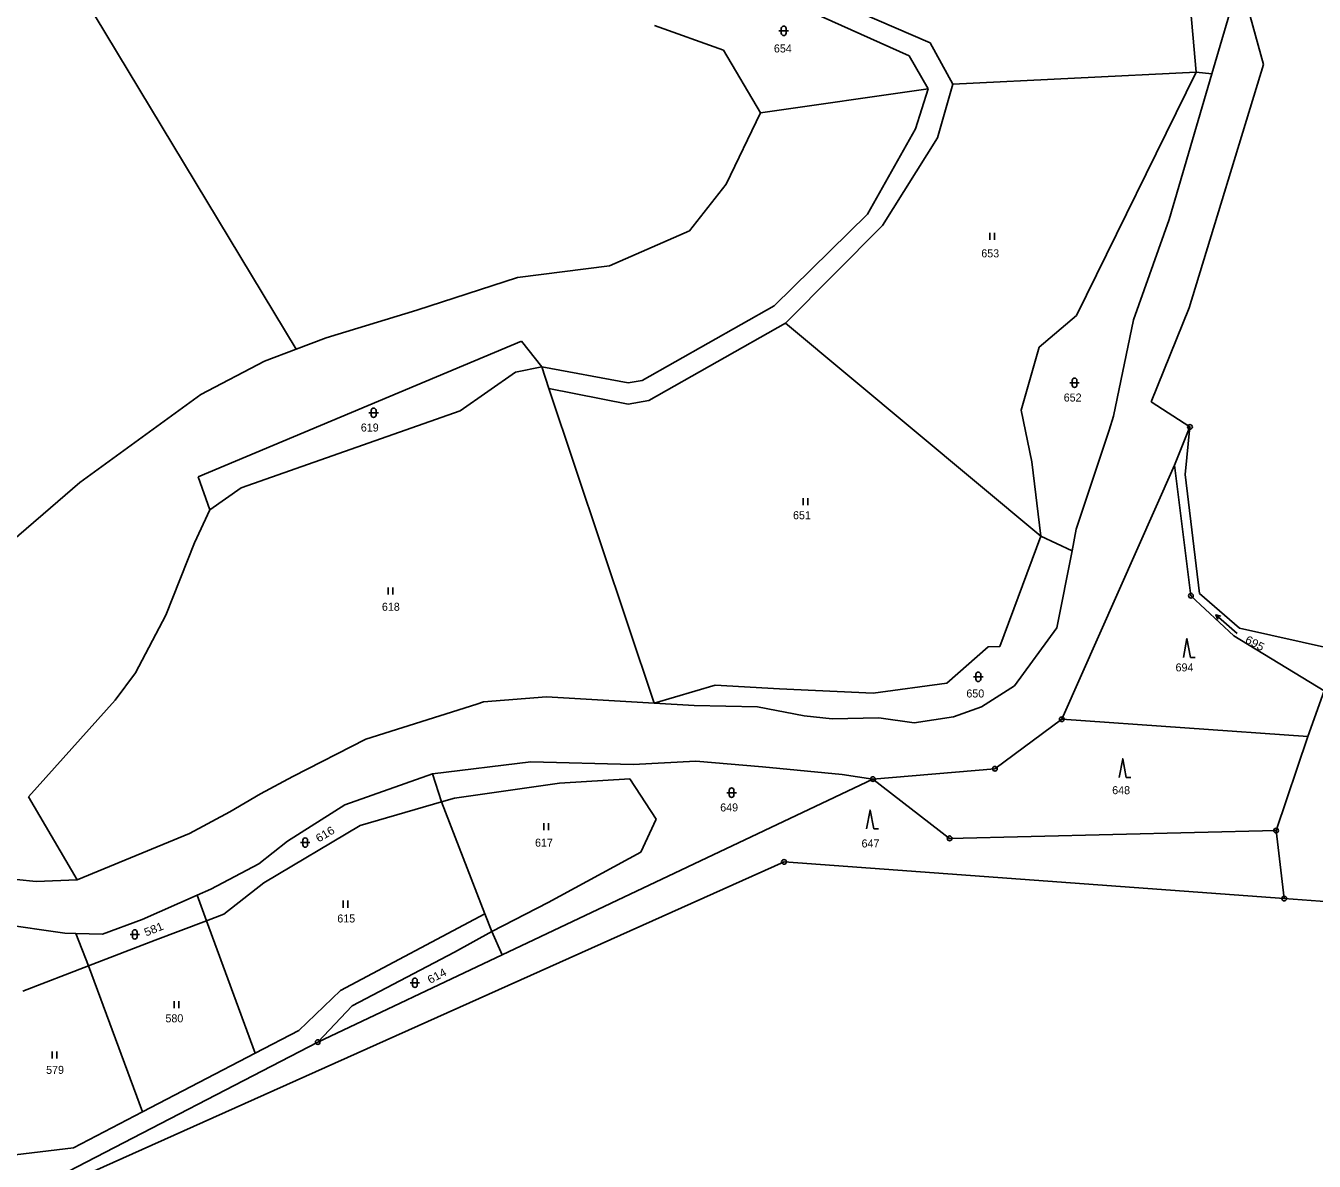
# Model space of a CAD drawing. Extents: x -719614 to -717765, y -1095834 to -1093862.
# Drawn here: x -718367.7 to -718094, y -1095270.4 to -1095029.2 of the extents above; entities that cross this region are included whole.
import ezdxf
from ezdxf.enums import TextEntityAlignment as Align

# ---------------------------------------------------------------- set-up
doc = ezdxf.new("R2010")
doc.units = 0
doc.header["$LTSCALE"] = 0.68
for name, color, linetype, lineweight in [('1', 7, 'Continuous', 25), ('3', 7, 'Continuous', 25), ('8', 7, 'Continuous', 25)]:
    doc.layers.add(name, color=color, linetype=linetype, lineweight=lineweight)
doc.layers.add('2', color=7, linetype='Continuous')

msp = doc.modelspace()

# ---------------------------------------------------------------- linework, layer by layer
at = {"layer": '1'}
for p, q in [((-718411.97, -1094929.43), (-718310.27, -1095097.96)), ((-718104.71, -1095037.45), (-718117.27, -1094991.94)), ((-718119.07, -1095039.08), (-718121.9, -1095005.89)), ((-718200.3, -1095022.15), (-718175.54, -1095032.85)), ((-718115.69, -1095039.42), (-718110.82, -1095022.82)), ((-718180.05, -1095035.63), (-718202.58, -1095025.52)), ((-718234.15, -1095029.17), (-718219.5, -1095034.4)), ((-718175.54, -1095032.85), (-718170.77, -1095041.63)), ((-718219.5, -1095034.4), (-718211.6, -1095047.71)), ((-718175.96, -1095042.61), (-718180.05, -1095035.63)), ((-718119.07, -1095039.08), (-718170.77, -1095041.63)), ((-718144.48, -1095090.75), (-718119.07, -1095039.08)), ((-718124.78, -1095070.37), (-718115.69, -1095039.42)), ((-718120.56, -1095089.14), (-718104.71, -1095037.45)), ((-718115.69, -1095039.42), (-718119.07, -1095039.08)), ((-718170.77, -1095041.63), (-718174, -1095053.08)), ((-718211.6, -1095047.71), (-718175.96, -1095042.61)), ((-718178.64, -1095051.16), (-718175.96, -1095042.61)), ((-718218.92, -1095062.91), (-718211.6, -1095047.71)), ((-718188.87, -1095069.23), (-718178.64, -1095051.16)), ((-718174, -1095053.08), (-718185.67, -1095071.69)), ((-718226.71, -1095072.82), (-718218.92, -1095062.91)), ((-718208.7, -1095088.7), (-718188.87, -1095069.23)), ((-718185.67, -1095071.69), (-718206.27, -1095092.4)), ((-718132.34, -1095091.7), (-718124.78, -1095070.37)), ((-718243.68, -1095080.21), (-718226.71, -1095072.82)), ((-718263.21, -1095082.68), (-718243.68, -1095080.21)), ((-718284.59, -1095089.64), (-718263.21, -1095082.68)), ((-718236.74, -1095104.56), (-718208.7, -1095088.7)), ((-718303.87, -1095095.53), (-718284.59, -1095089.64)), ((-718152.37, -1095097.54), (-718144.48, -1095090.75)), ((-718136.61, -1095112.17), (-718132.34, -1095091.7)), ((-718128.59, -1095109.11), (-718120.56, -1095089.14)), ((-718206.27, -1095092.4), (-718235.36, -1095108.86)), ((-718206.27, -1095092.4), (-718152.08, -1095137.64)), ((-718262.4, -1095096.22), (-718331.05, -1095125.06)), ((-718310.27, -1095097.96), (-718303.87, -1095095.53)), ((-718258.08, -1095101.67), (-718262.4, -1095096.22)), ((-718310.27, -1095097.96), (-718316.96, -1095100.51)), ((-718156.25, -1095110.88), (-718152.37, -1095097.54)), ((-718316.96, -1095100.51), (-718330.52, -1095107.59)), ((-718263.64, -1095102.8), (-718258.08, -1095101.67)), ((-718256.55, -1095106.32), (-718258.08, -1095101.67)), ((-718258.08, -1095101.67), (-718239.7, -1095105.09)), ((-718275.41, -1095111.05), (-718263.64, -1095102.8)), ((-718239.7, -1095105.09), (-718236.74, -1095104.56)), ((-718330.52, -1095107.59), (-718356.19, -1095126.27)), ((-718256.55, -1095106.32), (-718234.17, -1095173.14)), ((-718239.72, -1095109.64), (-718256.55, -1095106.32)), ((-718235.36, -1095108.86), (-718239.72, -1095109.64)), ((-718153.98, -1095121.83), (-718156.25, -1095110.88)), ((-718120.36, -1095114.46), (-718128.59, -1095109.11)), ((-718321.93, -1095127.37), (-718275.41, -1095111.05)), ((-718137.56, -1095115.12), (-718136.61, -1095112.17)), ((-718144.51, -1095136.14), (-718137.56, -1095115.12)), ((-718120.36, -1095114.46), (-718123.65, -1095122.55)), ((-718121.35, -1095124.53), (-718120.36, -1095114.46)), ((-718152.08, -1095137.64), (-718153.98, -1095121.83)), ((-718123.65, -1095122.55), (-718147.59, -1095176.52)), ((-718120.15, -1095150.29), (-718123.65, -1095122.55)), ((-718118.33, -1095149.81), (-718121.35, -1095124.53)), ((-718356.19, -1095126.27), (-718383.53, -1095149.71)), ((-718331.05, -1095125.06), (-718328.56, -1095132.05)), ((-718328.56, -1095132.05), (-718321.93, -1095127.37)), ((-718328.56, -1095132.05), (-718331.87, -1095139.09)), ((-718160.75, -1095161.05), (-718152.08, -1095137.64)), ((-718152.08, -1095137.64), (-718145.42, -1095140.75)), ((-718145.42, -1095140.75), (-718144.51, -1095136.14)), ((-718331.87, -1095139.09), (-718337.91, -1095154.42)), ((-718148.63, -1095157.1), (-718145.42, -1095140.75)), ((-718111.03, -1095158.79), (-718120.15, -1095150.29)), ((-718109.87, -1095157.2), (-718118.33, -1095149.81)), ((-718337.91, -1095154.42), (-718344.39, -1095166.71)), ((-718157.61, -1095169.47), (-718148.63, -1095157.1)), ((-718089.84, -1095161.63), (-718109.87, -1095157.2)), ((-718091.87, -1095170.5), (-718111.03, -1095158.79)), ((-718172.02, -1095168.85), (-718163.21, -1095161.15)), ((-718163.21, -1095161.15), (-718160.75, -1095161.05)), ((-718344.39, -1095166.71), (-718348.73, -1095172.5)), ((-718234.17, -1095173.14), (-718221.24, -1095169.31)), ((-718221.24, -1095169.31), (-718207.58, -1095170.06)), ((-718207.58, -1095170.06), (-718187.69, -1095171.03)), ((-718187.69, -1095171.03), (-718172.02, -1095168.85)), ((-718164.68, -1095173.89), (-718157.61, -1095169.47)), ((-718095.35, -1095180.18), (-718091.87, -1095170.5)), ((-718348.73, -1095172.5), (-718367.1, -1095192.98)), ((-718295.44, -1095180.73), (-718271.86, -1095173.32)), ((-718271.86, -1095173.32), (-718270.44, -1095172.81)), ((-718270.44, -1095172.81), (-718257.07, -1095171.78)), ((-718257.07, -1095171.78), (-718234.17, -1095173.14)), ((-718234.17, -1095173.14), (-718225.73, -1095173.64)), ((-718225.73, -1095173.64), (-718212.23, -1095173.89)), ((-718212.23, -1095173.89), (-718202.33, -1095175.83)), ((-718170.63, -1095176.05), (-718164.68, -1095173.89)), ((-718202.33, -1095175.83), (-718196.41, -1095176.44)), ((-718196.41, -1095176.44), (-718186.43, -1095176.25)), ((-718186.43, -1095176.25), (-718178.94, -1095177.33)), ((-718178.94, -1095177.33), (-718170.63, -1095176.05)), ((-718147.59, -1095176.52), (-718161.79, -1095187.06)), ((-718147.59, -1095176.52), (-718095.35, -1095180.18)), ((-718310.99, -1095188.71), (-718295.44, -1095180.73)), ((-718102.06, -1095200.19), (-718095.35, -1095180.18)), ((-718260.38, -1095185.55), (-718281.29, -1095188.13)), ((-718238.65, -1095186.13), (-718260.38, -1095185.55)), ((-718225.37, -1095185.46), (-718238.65, -1095186.13)), ((-718211.21, -1095186.67), (-718225.37, -1095185.46)), ((-718194.23, -1095188.28), (-718211.21, -1095186.67)), ((-718161.79, -1095187.06), (-718187.72, -1095189.24)), ((-718317.85, -1095192.35), (-718310.99, -1095188.71)), ((-718281.29, -1095188.13), (-718299.91, -1095194.71)), ((-718279.35, -1095194.1), (-718281.29, -1095188.13)), ((-718276.65, -1095193.32), (-718254.32, -1095190.13)), ((-718266.49, -1095226.55), (-718187.72, -1095189.24)), ((-718254.32, -1095190.13), (-718239.38, -1095189.17)), ((-718239.38, -1095189.17), (-718233.8, -1095197.73)), ((-718187.72, -1095189.24), (-718194.23, -1095188.28)), ((-718187.72, -1095189.24), (-718171.42, -1095201.83)), ((-718367.1, -1095192.98), (-718356.78, -1095210.62)), ((-718324.35, -1095196.22), (-718317.85, -1095192.35)), ((-718299.91, -1095194.71), (-718312.09, -1095202.45)), ((-718279.35, -1095194.1), (-718296.66, -1095199.12)), ((-718279.35, -1095194.1), (-718276.65, -1095193.32)), ((-718270.15, -1095217.87), (-718279.35, -1095194.1)), ((-718332.9, -1095200.78), (-718324.35, -1095196.22)), ((-718233.8, -1095197.73), (-718237.06, -1095204.8)), ((-718356.78, -1095210.62), (-718332.9, -1095200.78)), ((-718296.66, -1095199.12), (-718317.1, -1095211.28)), ((-718171.42, -1095201.83), (-718102.06, -1095200.19)), ((-718102.06, -1095200.19), (-718100.35, -1095214.61)), ((-718312.09, -1095202.45), (-718318.2, -1095207.21)), ((-718237.06, -1095204.8), (-718256.74, -1095215.46)), ((-718358.01, -1095274.64), (-718206.61, -1095206.83)), ((-718318.2, -1095207.21), (-718328.37, -1095212.59)), ((-718206.61, -1095206.83), (-718100.35, -1095214.61)), ((-718379.75, -1095209.59), (-718365.49, -1095210.98)), ((-718365.49, -1095210.98), (-718356.78, -1095210.62)), ((-718317.1, -1095211.28), (-718325.65, -1095217.94)), ((-718331.28, -1095213.89), (-718342.99, -1095219.1)), ((-718328.37, -1095212.59), (-718331.28, -1095213.89)), ((-718329.29, -1095219.32), (-718331.28, -1095213.89)), ((-718100.35, -1095214.61), (-718090.78, -1095215.31)), ((-718256.74, -1095215.46), (-718268.71, -1095221.61)), ((-718359.39, -1095221.98), (-718373.27, -1095219.99)), ((-718342.99, -1095219.1), (-718351.42, -1095222.2)), ((-718329.29, -1095219.32), (-718340.22, -1095223.45)), ((-718325.65, -1095217.94), (-718329.29, -1095219.32)), ((-718318.96, -1095247.49), (-718329.29, -1095219.32)), ((-718300.81, -1095234.15), (-718270.15, -1095217.87)), ((-718270.15, -1095217.87), (-718268.71, -1095221.61)), ((-718357.06, -1095222.04), (-718359.39, -1095221.98)), ((-718268.71, -1095221.61), (-718276.61, -1095225.99)), ((-718266.49, -1095226.55), (-718268.71, -1095221.61)), ((-718340.22, -1095223.45), (-718354.36, -1095228.91)), ((-718305.66, -1095245.1), (-718266.49, -1095226.55)), ((-718276.61, -1095225.99), (-718298.36, -1095237.38)), ((-718368.3, -1095234.29), (-718354.36, -1095228.91)), ((-718354.36, -1095228.91), (-718342.9, -1095259.91)), ((-718309.67, -1095242.67), (-718300.81, -1095234.15)), ((-718298.36, -1095237.38), (-718305.66, -1095245.1)), ((-718358.69, -1095272.6), (-718305.66, -1095245.1)), ((-718318.96, -1095247.49), (-718309.67, -1095242.67)), ((-718342.9, -1095259.91), (-718318.96, -1095247.49)), ((-718357.59, -1095267.53), (-718342.9, -1095259.91)), ((-718371.73, -1095269.28), (-718357.59, -1095267.53))]:
    msp.add_line(p, q, dxfattribs=at)
msp.add_lwpolyline([(-718351.42, -1095222.2), (-718357.06, -1095222.04), (-718354.36, -1095228.91)], dxfattribs=at)
at = {"layer": '3'}
for p, q in [((-718207.681, -1095030.321), (-718205.679, -1095030.321)), ((-718207.181, -1095029.821), (-718207.181, -1095030.822)), ((-718206.179, -1095030.822), (-718206.179, -1095029.821)), ((-718162.871, -1095074.7), (-718162.871, -1095073.2)), ((-718161.87, -1095074.7), (-718161.87, -1095073.2)), ((-718145.871, -1095105.071), (-718143.869, -1095105.071)), ((-718145.371, -1095104.571), (-718145.371, -1095105.572)), ((-718144.369, -1095105.572), (-718144.369, -1095104.571)), ((-718294.291, -1095110.941), (-718294.291, -1095111.942)), ((-718293.289, -1095111.942), (-718293.289, -1095110.941)), ((-718294.791, -1095111.441), (-718292.789, -1095111.441)), ((-718202.521, -1095131.07), (-718202.521, -1095129.57)), ((-718201.52, -1095131.07), (-718201.52, -1095129.57)), ((-718290.731, -1095150.03), (-718290.731, -1095148.53)), ((-718289.73, -1095150.03), (-718289.73, -1095148.53)), ((-718114.861, -1095154.354), (-718113.795, -1095154.617)), ((-718120.25, -1095163.39), (-718119.254, -1095163.39)), ((-718166.331, -1095167.521), (-718164.329, -1095167.521)), ((-718165.831, -1095167.021), (-718165.831, -1095168.022)), ((-718164.829, -1095168.022), (-718164.829, -1095167.021)), ((-718133.89, -1095188.92), (-718132.894, -1095188.92)), ((-718218.741, -1095192.131), (-718216.739, -1095192.131)), ((-718218.241, -1095191.631), (-718218.241, -1095192.632)), ((-718217.239, -1095192.632), (-718217.239, -1095191.631)), ((-718257.661, -1095200.1), (-718257.661, -1095198.6)), ((-718256.66, -1095200.1), (-718256.66, -1095198.6)), ((-718187.56, -1095199.84), (-718186.564, -1095199.84)), ((-718309.331, -1095202.721), (-718307.329, -1095202.721)), ((-718308.831, -1095202.221), (-718308.831, -1095203.222)), ((-718307.829, -1095203.222), (-718307.829, -1095202.221)), ((-718300.261, -1095216.56), (-718300.261, -1095215.06)), ((-718299.26, -1095216.56), (-718299.26, -1095215.06)), ((-718345.551, -1095222.231), (-718343.549, -1095222.231)), ((-718345.051, -1095221.731), (-718345.051, -1095222.732)), ((-718344.049, -1095222.732), (-718344.049, -1095221.731)), ((-718286.021, -1095232.501), (-718284.019, -1095232.501)), ((-718285.521, -1095232.001), (-718285.521, -1095233.002)), ((-718284.519, -1095233.002), (-718284.519, -1095232.001)), ((-718336.201, -1095237.92), (-718336.201, -1095236.42)), ((-718335.2, -1095237.92), (-718335.2, -1095236.42)), ((-718362.111, -1095248.6), (-718362.111, -1095247.1)), ((-718361.11, -1095248.6), (-718361.11, -1095247.1))]:
    msp.add_line(p, q, dxfattribs=at)
for points in [[(-718110.333, -1095158.29), (-718114.861, -1095154.354), (-718114.453, -1095155.374)], [(-718120.25, -1095163.39), (-718121, -1095159.39), (-718121.75, -1095163.39)], [(-718133.89, -1095188.92), (-718134.64, -1095184.92), (-718135.39, -1095188.92)], [(-718187.56, -1095199.84), (-718188.31, -1095195.84), (-718189.06, -1095199.84)]]:
    msp.add_lwpolyline(points, dxfattribs=at)
for centre, start, end in [((-718206.68, -1095029.8209), 0, 180), ((-718206.68, -1095030.8209), 180, 359.98789), ((-718144.87, -1095104.5709), 0, 180), ((-718144.87, -1095105.5709), 180, 359.98789), ((-718293.79, -1095110.9409), 0, 180), ((-718293.79, -1095111.9409), 180, 359.98789), ((-718165.33, -1095167.0209), 0, 180), ((-718165.33, -1095168.0209), 180, 359.98789), ((-718217.74, -1095191.6309), 0, 180), ((-718217.74, -1095192.6309), 180, 359.98789), ((-718308.33, -1095202.2209), 0, 180), ((-718308.33, -1095203.2209), 180, 359.98789), ((-718344.55, -1095221.7309), 0, 180), ((-718344.55, -1095222.7309), 180, 359.98789), ((-718285.02, -1095232.0009), 0, 180), ((-718285.02, -1095233.0009), 180, 359.98789)]:
    msp.add_arc(centre, 0.5, start, end, dxfattribs=at)
at = {"layer": '8'}
for centre, radius in [((-718120.36, -1095114.4599), 0.5), ((-718120.36, -1095114.4599), 0.0303), ((-718120.15, -1095150.2899), 0.5), ((-718120.15, -1095150.2899), 0.0303), ((-718147.59, -1095176.5199), 0.5), ((-718147.59, -1095176.5199), 0.0303), ((-718161.79, -1095187.0599), 0.5), ((-718161.79, -1095187.0599), 0.0303), ((-718187.72, -1095189.2399), 0.5), ((-718187.72, -1095189.2399), 0.0303), ((-718102.06, -1095200.1899), 0.5), ((-718102.06, -1095200.1899), 0.0303), ((-718171.42, -1095201.8299), 0.5), ((-718171.42, -1095201.8299), 0.0303), ((-718206.61, -1095206.8299), 0.5), ((-718206.61, -1095206.8299), 0.0303), ((-718100.35, -1095214.6099), 0.5), ((-718100.35, -1095214.6099), 0.0303), ((-718305.66, -1095245.0999), 0.5), ((-718305.66, -1095245.0999), 0.0303)]:
    msp.add_circle(centre, radius, dxfattribs=at)

# ---------------------------------------------------------------- texts
at = {"layer": '2'}
for s, p in [('654', (-718206.859, -1095034.912)), ('653', (-718162.799, -1095078.432)), ('652', (-718145.289, -1095109.052)), ('619', (-718294.619, -1095115.422)), ('651', (-718202.799, -1095134.052)), ('618', (-718290.139, -1095153.502)), ('694', (-718121.529, -1095166.372)), ('650', (-718165.969, -1095171.912)), ('648', (-718134.989, -1095192.452)), ('649', (-718218.269, -1095196.112)), ('617', (-718257.609, -1095203.592)), ('647', (-718188.239, -1095203.762)), ('615', (-718299.619, -1095219.702)), ('580', (-718336.129, -1095240.902)), ('579', (-718361.479, -1095251.852))]:
    msp.add_text(s, height=1.7, dxfattribs=at).set_placement(p, align=Align.CENTER)
at = {"layer": '2', "width": 1.1}
for s, rotation, p in [('695', 332, (-718106.9681, -1095161.1399)), ('616', 31, (-718303.6768, -1095201.6655)), ('581', 22, (-718340.2064, -1095221.9131)), ('614', 28, (-718279.9541, -1095231.7941))]:
    msp.add_text(s, height=1.7, rotation=rotation, dxfattribs=at).set_placement(p, align=Align.CENTER)

doc.saveas('drawing.dxf')
